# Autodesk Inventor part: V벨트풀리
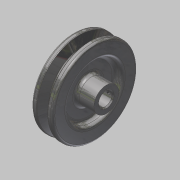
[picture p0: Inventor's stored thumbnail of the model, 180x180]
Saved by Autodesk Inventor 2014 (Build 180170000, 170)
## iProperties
Created: 2015-11
Part Number: V벨트풀리
Material: 강철, 탄소
Document SubType Name: Modeling
Designer: mduedu
Density: 1 g/cm^3
Appearance: 반광택
Author: mduedu
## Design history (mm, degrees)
sketch "스케치1"
  geometry: L1 (-9.5, 0)-(9.5, 0); L2 (0, 0)-(0, 37.7); L3 (-4.825, 37.7)-(-9.5, 37.7); L4 (-9.5, 37.7)-(-9.5, 0); L5 (0, 28.7)-(-2.074, 28.7); L6 (-2.074, 28.7)-(-4.825, 37.7); L7 (4.825, 37.7)-(9.5, 37.7); L8 (9.5, 37.7)-(9.5, 0); L9 (0, 28.7)-(2.074, 28.7); L10 (2.074, 28.7)-(4.825, 37.7); L11 (-9.5, 35)-(9.5, 35); 3 further points
  constraints: 22 end point, 7 point on line, 4 perpendicular, 3 symmetric about line, 1 coincident, 1 horizontal, 1 horizontal alignment, 1 midpoint, 1 vertical
  dimensions: "d0" = 19 distance of L1.start L1.end; "d2" = 75.4 diameter of L2.end L1 (derived); "d3" = 34 deg angle of L10 L6; "d4" = 6.3 distance between parallel lines of L11 L9; "d5" = 2.7 distance between parallel lines of L7 L11; "d6" = 8 distance of point (4, 35) point (-4, 35); "d7" = 70 diameter of L11 L1
revolve "회전1" sketch "스케치1" stored, may be unused: angle "d8" = 90 deg
sketch "스케치2"
  geometry: C1 r 24 at (0, 0); C2 r 11 at (0, 0); 1 further point
  constraints: 2 centre point, 2 coincident
  dimensions: "d9" = 48 diameter of C1; "d10" = 22 diameter of C2
extrude "돌출1" cut sketch "스케치2" distance "d11" = 6; taper "d12" = 0 deg
extrude "돌출3" join sketch "스케치2" distance "d37" = 10; taper "d38" = 0 deg
fillet "모깎기1" dims "d13" = 3
fillet "모깎기2" dims "d14" = 3
fillet "모깎기3" dims "d15" = 1, "d16" = 0.5, "d17" = 2
hole "구멍1" diameter "d20" = 12; stored, may be unused: countersink angle "d24" = 90 deg, drill point angle "d26" = 118 deg; dims "d21" = 6, "d22" = 4, "d23" = 2, "d25" = 8, "d39" = 10, "d40" = 10
sketch "스케치3"
  geometry: L1 (-2, 0)-(2, 0); L2 (2, 0)-(2, 7.8); L3 (2, 7.8)-(-2, 7.8); L4 (-2, 7.8)-(-2, 0); 2 further points
  constraints: 8 end point, 2 parallel, 1 coincident, 1 horizontal, 1 midpoint, 1 perpendicular
  dimensions: "d27" = 4 distance of L2.end L3.end; "d29" = 7.8 distance of L3.end L1.start
extrude "돌출2" cut sketch "스케치3" stored distance "d30" = 6; taper "d31" = 0 deg
chamfer "모따기1" distance "d32" = 1; stored, may be unused: second distance "d33" = 2, angle "d34" = 45 deg
node "작업 평면1"
sketch "스케치4"
  geometry: L1 (-19, 11)-(-19, -11) reference; 2 further points
  constraints: 1 horizontal alignment
  dimensions: "d41" = 25 distance from line of point (6, 0) L1
hole "구멍2" sketch "스케치4" at (6, 0) diameter "d42" = 2.459; stored, may be unused: countersink angle "d46" = 90 deg, drill point angle "d48" = 118 deg; dims "d43" = 6, "d44" = 4, "d45" = 2, "d47" = 8
chamfer "모따기2" distance "d49" = 1; stored, may be unused: second distance "d50" = 2, angle "d51" = 45 deg
node "솔리드1"
mirror "대칭1"
